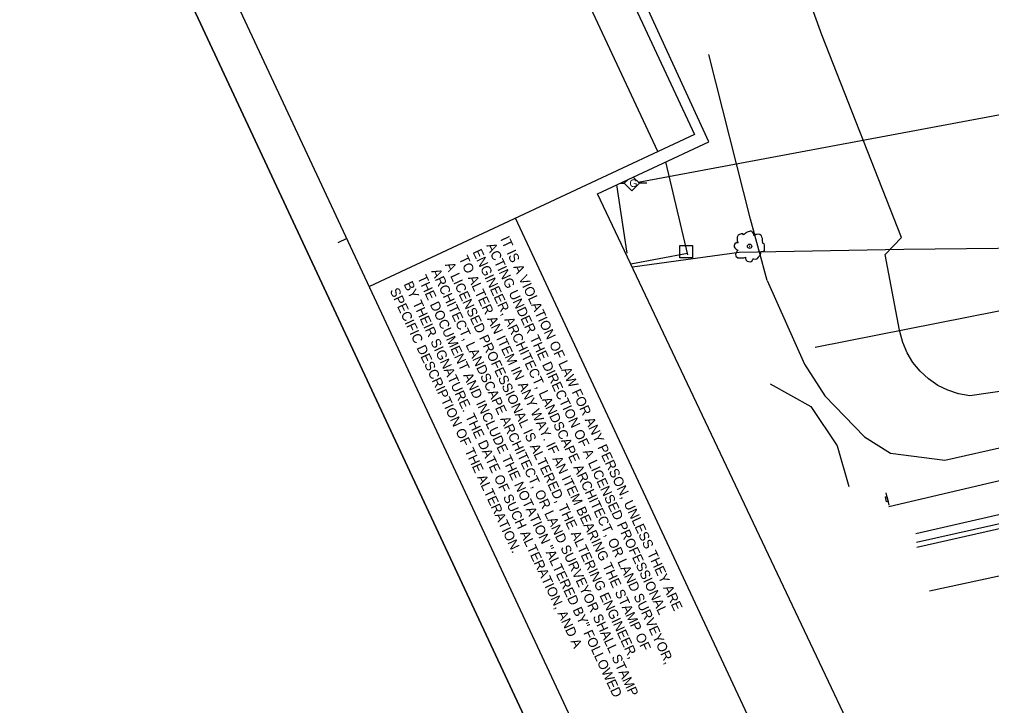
# Model space of a CAD drawing. Extents: x 1040567 to 1041254, y 1126791 to 1127594.
# Drawn here: x 1040567.2 to 1040808.5, y 1127141.8 to 1127312.2 of the extents above; entities that cross this region are included whole.
import ezdxf

# ---------------------------------------------------------------- set-up
doc = ezdxf.new("R2010")
doc.units = 0
for name, color, linetype in [('clip boundary', 7, 'Continuous'), ('LELB', 7, 'Continuous'), ('LFNC', 7, 'Continuous'), ('LTD', 7, 'Continuous'), ('MHB', 7, 'Continuous'), ('MPM', 7, 'Continuous'), ('PE', 7, 'Continuous'), ('PET', 7, 'Continuous'), ('RDU', 7, 'Continuous'), ('RELB', 7, 'Continuous'), ('SDEL', 7, 'Continuous'), ('SHEET_BORDER', 7, 'Continuous'), ('SHEET_BORDER_CUT', 7, 'Continuous'), ('SHEET_BORDER_STAMPBOX', 7, 'Continuous'), ('STBW', 7, 'Continuous'), ('STSEW', 7, 'Continuous'), ('UFO', 7, 'Continuous'), ('UG', 7, 'Continuous'), ('UGMK', 7, 'Continuous')]:
    doc.layers.add(name, color=color, linetype=linetype)

msp = doc.modelspace()

# ---------------------------------------------------------------- linework, layer by layer
at = {"layer": 'clip boundary'}
for points in [[(1040965.89, 1127593.65), (1041253.68, 1126977.55), (1040855.03, 1126791.33), (1040567.24, 1127407.43)], [(1040984.84, 1127512.73), (1041214.88, 1127013.05), (1040933.62, 1126879.17), (1040829.04, 1127018.95), (1040710.75, 1127268.88), (1040738.34, 1127281.77), (1040695.57, 1127374.92)]]:
    msp.add_lwpolyline(points, close=True, dxfattribs=at)
at = {"layer": 'LELB'}
for points in [[(1040766.38, 1127308.3), (1040751.85, 1127348.64), (1040740.09, 1127396.13)], [(1040786.14, 1127258), (1040766.38, 1127308.3)], [(1040748.72, 1127262.54), (1040738.38, 1127303.47)], [(1040718.05, 1127254.1), (1040715.51, 1127271.1)], [(1040752.79, 1127247.3), (1040748.72, 1127262.54)], [(1040782.14, 1127253.75), (1040786.14, 1127258)], [(1040880.09, 1127235.94), (1040871.78, 1127231.85), (1040851.81, 1127226.09), (1040822.45, 1127221.53), (1040803.09, 1127218.72), (1040800.33, 1127219.2), (1040797.67, 1127220.07), (1040795.15, 1127221.3), (1040792.84, 1127222.88), (1040790.78, 1127224.78), (1040789.01, 1127226.95), (1040787.56, 1127229.35), (1040786.47, 1127231.93), (1040785.76, 1127234.64), (1040785.69, 1127235.03), (1040782.14, 1127253.75)], [(1040752.79, 1127247.3), (1040762.05, 1127226.54), (1040767.16, 1127218.68), (1040776.98, 1127208.49), (1040783.41, 1127204.47), (1040796.88, 1127202.69), (1040813.08, 1127206.37), (1040834.72, 1127210.86), (1040861.57, 1127217.43), (1040890.65, 1127224.61)]]:
    msp.add_lwpolyline(points, dxfattribs=at)
at = {"layer": 'LFNC'}
msp.add_lwpolyline([(1040868.77, 1127256.35), (1040833.36, 1127255.5), (1040786.73, 1127254.99), (1040745.87, 1127254.28), (1040719.39, 1127250.62)], dxfattribs=at)
at = {"layer": 'LTD'}
for points in [[(1040752.04, 1127256.44), (1040751.78, 1127256.54), (1040751.68, 1127256.66), (1040751.72, 1127256.75), (1040751.65, 1127257.17), (1040751.65, 1127257.73), (1040751.53, 1127258.12), (1040751.38, 1127258.43), (1040751.02, 1127258.79), (1040750.75, 1127258.85), (1040750.22, 1127258.79), (1040750.01, 1127258.73), (1040749.61, 1127258.52), (1040749.55, 1127258.49), (1040749.49, 1127258.7), (1040749.43, 1127259.03), (1040749.22, 1127259.33), (1040749.01, 1127259.49), (1040748.83, 1127259.58), (1040748.59, 1127259.58), (1040748.4, 1127259.49), (1040748.1, 1127259.39), (1040747.86, 1127259.33), (1040747.56, 1127259.15), (1040747.41, 1127258.97), (1040746.97, 1127258.7), (1040746.76, 1127258.88), (1040746.33, 1127258.88), (1040745.82, 1127258.7), (1040745.61, 1127258.55), (1040745.4, 1127258.08), (1040745.34, 1127257.63), (1040745.34, 1127257.2), (1040745.46, 1127256.9), (1040745.61, 1127256.66)], [(1040745.61, 1127256.66), (1040745.15, 1127256.72), (1040744.79, 1127256.42), (1040744.67, 1127256.02), (1040744.67, 1127255.72), (1040744.79, 1127255.42), (1040745.12, 1127255.09), (1040745.37, 1127254.97), (1040745.58, 1127254.9), (1040745.43, 1127254.72), (1040745.31, 1127254.54), (1040744.94, 1127253.89), (1040745.06, 1127253.35), (1040745.52, 1127252.98), (1040745.82, 1127252.95), (1040746.45, 1127252.95), (1040747, 1127252.98), (1040747.41, 1127253.11), (1040747.41, 1127252.89), (1040747.56, 1127252.47), (1040747.68, 1127252.26), (1040747.86, 1127252.14), (1040748.19, 1127252.02), (1040748.62, 1127251.99), (1040748.83, 1127252.02), (1040749.13, 1127252.2), (1040749.28, 1127252.59), (1040749.31, 1127252.74), (1040749.49, 1127252.71), (1040749.92, 1127252.65), (1040750.28, 1127252.74), (1040750.4, 1127252.83), (1040750.7, 1127253.14), (1040750.79, 1127253.26), (1040751.02, 1127253.53), (1040751.14, 1127253.71), (1040751.23, 1127254.04), (1040751.2, 1127254.48), (1040751.41, 1127254.51), (1040752.16, 1127254.67)], [(1040748.51, 1127255.84), (1040748.51, 1127255.84), (1040748.51, 1127255.84), (1040748.51, 1127255.86), (1040748.51, 1127255.86), (1040748.51, 1127255.86), (1040748.51, 1127255.87), (1040748.49, 1127255.87), (1040748.49, 1127255.87), (1040748.49, 1127255.87), (1040748.49, 1127255.87), (1040748.49, 1127255.89), (1040748.48, 1127255.89), (1040748.48, 1127255.89), (1040748.48, 1127255.89), (1040748.46, 1127255.89), (1040748.46, 1127255.89), (1040748.46, 1127255.89), (1040748.45, 1127255.89), (1040748.45, 1127255.89), (1040748.45, 1127255.89), (1040748.43, 1127255.89), (1040748.43, 1127255.87), (1040748.43, 1127255.87), (1040748.43, 1127255.87), (1040748.42, 1127255.87), (1040748.42, 1127255.87), (1040748.42, 1127255.86), (1040748.42, 1127255.86), (1040748.42, 1127255.86), (1040748.42, 1127255.84), (1040748.42, 1127255.84), (1040748.42, 1127255.84), (1040748.42, 1127255.83), (1040748.42, 1127255.83), (1040748.42, 1127255.83), (1040748.42, 1127255.81), (1040748.42, 1127255.81), (1040748.43, 1127255.81), (1040748.43, 1127255.81), (1040748.43, 1127255.8), (1040748.43, 1127255.8), (1040748.45, 1127255.8), (1040748.45, 1127255.8), (1040748.45, 1127255.8), (1040748.46, 1127255.8), (1040748.46, 1127255.8), (1040748.46, 1127255.8), (1040748.48, 1127255.8), (1040748.48, 1127255.8), (1040748.48, 1127255.8), (1040748.49, 1127255.8), (1040748.49, 1127255.8), (1040748.49, 1127255.81), (1040748.49, 1127255.81), (1040748.49, 1127255.81), (1040748.51, 1127255.81), (1040748.51, 1127255.83), (1040748.51, 1127255.83), (1040748.51, 1127255.83), (1040748.51, 1127255.84)], [(1040752.16, 1127254.67), (1040752.2, 1127255.24), (1040752.2, 1127255.72), (1040752.14, 1127256.14), (1040752.04, 1127256.44)]]:
    msp.add_lwpolyline(points, dxfattribs=at)
msp.add_circle((1040748.46, 1127255.84), 0.533, dxfattribs=at)
at = {"layer": 'MHB'}
for points in [[(1040733.14, 1127253.68), (1040727.63, 1127276.76)], [(1040718.97, 1127251.51), (1040733.04, 1127254.1)]]:
    msp.add_lwpolyline(points, dxfattribs=at)
at = {"layer": 'MPM'}
for p, q in [((1040731.17, 1127252.93), (1040731.17, 1127256)), ((1040731.17, 1127256), (1040734.32, 1127256)), ((1040734.32, 1127256), (1040734.32, 1127252.93)), ((1040734.32, 1127252.93), (1040731.17, 1127252.93))]:
    msp.add_line(p, q, dxfattribs=at)
at = {"layer": 'PE'}
msp.add_lwpolyline([(1040918.96, 1127220.52), (1040889.79, 1127215.06), (1040861.88, 1127209.08), (1040835.08, 1127203.24), (1040808.72, 1127197.17), (1040783, 1127191.17)], dxfattribs=at)
at = {"layer": 'PET'}
msp.add_lwpolyline([(1040898.45, 1127206.84), (1040851.51, 1127196.13), (1040789.92, 1127182.31)], dxfattribs=at)
at = {"layer": 'RDU'}
for points in [[(1040762.05, 1127226.54), (1040767.16, 1127218.68), (1040776.98, 1127208.49), (1040783.41, 1127204.47), (1040796.88, 1127202.69), (1040813.08, 1127206.37), (1040834.72, 1127210.86), (1040861.57, 1127217.43), (1040890.65, 1127224.61)], [(1040753.58, 1127221.71), (1040763.65, 1127216.01), (1040770.21, 1127206.29), (1040773.13, 1127196.16)]]:
    msp.add_lwpolyline(points, dxfattribs=at)
at = {"layer": 'RELB'}
msp.add_lwpolyline([(1040789.72, 1127184.52), (1040850.81, 1127198.51), (1040897.68, 1127208.75)], dxfattribs=at)
at = {"layer": 'SDEL'}
msp.add_line((1040783.07, 1127191.56), (1040782.34, 1127194.62), dxfattribs=at)
msp.add_lwpolyline([(1040782.56, 1127193.71), (1040782.85, 1127192.47), (1040782.48, 1127192.38), (1040782.19, 1127193.62)], close=True, dxfattribs=at)
at = {"layer": 'SHEET_BORDER'}
msp.add_line((1040648.53, 1127257.77), (1040646.26, 1127256.71), dxfattribs=at)
msp.add_lwpolyline([(1040856.06, 1126819.41), (1040852.74, 1126820.61), (1040588.22, 1127386.88), (1040589.43, 1127390.2), (1040964.86, 1127565.58), (1040968.18, 1127564.37), (1041232.7, 1126998.11), (1041231.49, 1126994.78)], close=True, dxfattribs=at)
at = {"layer": 'SHEET_BORDER_CUT'}
msp.add_lwpolyline([(1040567.24, 1127407.43), (1040855.03, 1126791.33), (1041253.68, 1126977.55), (1040965.89, 1127593.65)], close=True, dxfattribs=at)
at = {"layer": 'SHEET_BORDER_STAMPBOX'}
for p, q in [((1040667.85, 1127426.84), (1040734.78, 1127283.57)), ((1040725.72, 1127279.34), (1040658.79, 1127422.6)), ((1040734.78, 1127283.57), (1040654.08, 1127245.88)), ((1040747.91, 1127139.53), (1040690.32, 1127262.81))]:
    msp.add_line(p, q, dxfattribs=at)
at = {"layer": 'STBW'}
msp.add_lwpolyline([(1040793.12, 1127170.28), (1040855.25, 1127183.65), (1040900.52, 1127193.94)], dxfattribs=at)
at = {"layer": 'STSEW'}
msp.add_lwpolyline([(1040898.34, 1127205.46), (1040851.87, 1127195.04), (1040789.94, 1127181.07)], dxfattribs=at)
at = {"layer": 'UFO'}
msp.add_lwpolyline([(1040764.75, 1127230.79), (1040863, 1127250.2), (1040889.01, 1127252.29), (1040959.97, 1127266.63), (1041031.5, 1127295.51), (1041079.55, 1127307.01)], dxfattribs=at)
at = {"layer": 'UG'}
msp.add_line((1040720.8, 1127271.78), (1040807.58, 1127288), dxfattribs=at)
msp.add_lwpolyline([(1040807.58, 1127288), (1040878.42, 1127301.33), (1040950.7, 1127315.88), (1041023.78, 1127336.91)], dxfattribs=at)
at = {"layer": 'UGMK'}
for p, q in [((1040719.58, 1127273), (1040721.1, 1127271.48)), ((1040717.33, 1127271.48), (1040718.2, 1127272.35)), ((1040719.22, 1127269.59), (1040717.33, 1127271.48)), ((1040721.1, 1127271.48), (1040719.22, 1127269.59))]:
    msp.add_line(p, q, dxfattribs=at)
for points in [[(1040716.33, 1127271.48), (1040717.33, 1127271.48)], [(1040722.99, 1127271.48), (1040721.1, 1127271.48)]]:
    msp.add_lwpolyline(points, dxfattribs=at)

# ---------------------------------------------------------------- texts
at = {"layer": 'SHEET_BORDER_STAMPBOX'}
for s, p in [('IT IS A VIOLATION OF LAW FOR ANY PERSON, UNLESS THEY ARE ', (1040686.51, 1127257.65)), ('ACTING UNDER THE DIRECTION OF A LICENSED PROFESSIONAL ', (1040683.08, 1127256.04)), ('TO ALTER AN ITEM IN ANY WAY. IF AN ITEM BEARING THE STAMP OF ', (1040676.23, 1127252.84)), ('ENGINEER, ARCHITECT, LANDSCAPE ARCHITECT, OR LAND SURVEYOR, ', (1040679.66, 1127254.44)), ('A LICENSED PROFESSIONAL IS ALTERED, THE ALTERING ENGINEER, ', (1040672.81, 1127251.24)), ('THE DOCUMENT AND INCLUDE THE NOTATION "ALTERED BY" FOLLOWED ', (1040665.95, 1127248.04)), ('ARCHITECT, LANDSCAPE ARCHITECT, OR LAND SURVEYOR SHALL STAMP ', (1040669.38, 1127249.64)), ('BY THEIR SIGNATURE. THE DATE OF SUCH ALTERATION, AND A ', (1040662.53, 1127246.44)), ('SPECIFIC DESCRIPTION OF THE ALTERATION.', (1040659.1, 1127244.84))]:
    msp.add_text(s, height=2.4, rotation=295.0387, dxfattribs=at).set_placement(p)
at = {"layer": 'UGMK'}
msp.add_text('G', height=1.89, rotation=360, dxfattribs=at).set_placement((1040718.65, 1127270.54))

doc.saveas('drawing.dxf')
